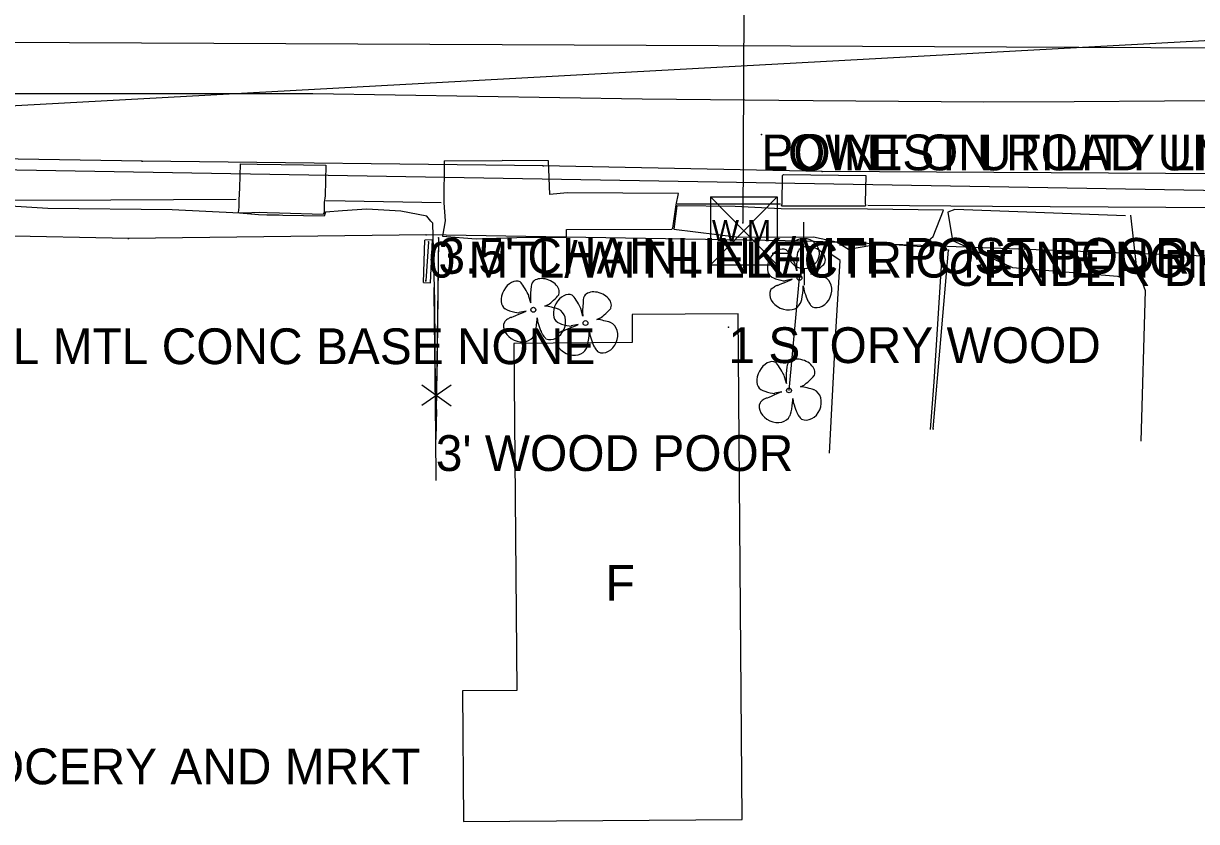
# Model space of a CAD drawing. Extents: x 1304270 to 1306561, y 1876019 to 1876752.
# Drawn here: x 1305136 to 1305299.9, y 1876306.3 to 1876417.9 of the extents above; entities that cross this region are included whole.
import ezdxf

# ---------------------------------------------------------------- set-up
doc = ezdxf.new("R2010")
doc.units = 0
for name, color, linetype in [('Default', 7, 'Continuous'), ('S_BUILDING', 7, 'Continuous'), ('S_BUILDING_ANNOT', 7, 'Continuous'), ('S_DRIVEWAY', 7, 'Continuous'), ('S_EDGE_CONCRETE', 7, 'Continuous'), ('S_EDGE_PAVEMENT', 7, 'Continuous'), ('S_ELECTRIC_UTILITIES_ANNOT', 7, 'Continuous'), ('S_FENCE', 7, 'Continuous'), ('S_FENCE_ANNOT', 7, 'Continuous'), ('S_FIBER_OPTIC_CABLE', 7, 'Continuous'), ('S_GAS_UTILITIES', 7, 'Continuous'), ('S_MISC_STRUCTURES', 7, 'Continuous'), ('S_MISC_STRUCTURES_ANNOT', 7, 'Continuous'), ('S_MSC_PT_SYM', 7, 'Continuous'), ('S_PAVEMENT_CROWN', 7, 'Continuous'), ('S_SANITARY_SEWER', 7, 'Continuous'), ('S_SHOULDER', 7, 'Continuous'), ('S_SIGN', 7, 'Continuous'), ('S_SIGN_ANNOT', 7, 'Continuous'), ('S_STR_PT_SYM', 7, 'Continuous'), ('S_SURVEY_TEXT_ANNOT', 7, 'Continuous'), ('S_TREE', 7, 'Continuous'), ('S_UTILITY_POLE', 7, 'Continuous'), ('S_UTL_PT_SYM', 7, 'Continuous'), ('S_WATER_UTILITIES', 7, 'Continuous')]:
    doc.layers.add(name, color=color, linetype=linetype)

msp = doc.modelspace()

# ---------------------------------------------------------------- linework, layer by layer
at = {"layer": 'Default'}
msp.add_line((1304873.94, 1876392.06), (1305473.53, 1876424.94), dxfattribs=at)
at = {"layer": 'S_BUILDING'}
msp.add_lwpolyline([(1305236.42, 1876306.65), (1305235.86, 1876377.3), (1305221.06, 1876377.18), (1305221.09, 1876373.28), (1305204.56, 1876373.15), (1305204.95, 1876324.66), (1305197.36, 1876324.6), (1305197.5, 1876306.34)], close=True, dxfattribs=at)
at = {"layer": 'S_DRIVEWAY'}
for points in [[(1305290.67, 1876391.05), (1305291.49, 1876384.02), (1305292.72, 1876380.55), (1305292.14, 1876359.47)], [(1305248.63, 1876357.79), (1305249.51, 1876374.72), (1305250.14, 1876384.75), (1305248.83, 1876385.6)], [(1305264.44, 1876386.92), (1305263.21, 1876367.8), (1305262.7, 1876361.12)]]:
    msp.add_lwpolyline(points, dxfattribs=at)
at = {"layer": 'S_EDGE_CONCRETE'}
for points in [[(1305194.83, 1876398.65), (1305194.76, 1876392.78), (1305194.93, 1876390.27), (1305194.57, 1876388.15), (1305199.27, 1876387.78), (1305206.42, 1876388.01), (1305211.9, 1876387.93), (1305211.92, 1876389.06), (1305226.59, 1876389.12), (1305226.74, 1876389.23), (1305227.2, 1876392.52), (1305227.53, 1876394.09), (1305212.01, 1876394.2), (1305209.58, 1876393.96), (1305209.39, 1876398.66), (1305202.9, 1876398.72)], [(1305194.83, 1876398.65), (1305202.9, 1876398.72)], [(1305166.1, 1876391.45), (1305166.16, 1876392.2), (1305166.18, 1876392.58), (1305166.2, 1876393.14), (1305166.25, 1876394.88), (1305166.36, 1876398.22), (1305168.68, 1876398.19), (1305172.03, 1876398.16), (1305178.27, 1876398.07), (1305178.18, 1876393.78), (1305178.07, 1876392.83), (1305178.07, 1876392.17), (1305178.07, 1876391.48), (1305177.9, 1876391.15), (1305171.83, 1876391.36), (1305170.07, 1876391.4), (1305169.01, 1876391.44), (1305167.97, 1876391.41)], [(1305241.95, 1876392.35), (1305242.01, 1876392.65), (1305242.07, 1876396.61), (1305242.2, 1876396.73), (1305253.69, 1876396.59), (1305253.63, 1876392.8), (1305253.64, 1876392.39)], [(1305241.95, 1876392.35), (1305253.64, 1876392.39)], [(1305166.1, 1876391.45), (1305167.97, 1876391.41)], [(1305191.92, 1876381.68), (1305192.91, 1876381.59), (1305193.18, 1876387.64), (1305192.11, 1876387.59)], [(1305191.92, 1876381.68), (1305192.11, 1876387.59)]]:
    msp.add_lwpolyline(points, dxfattribs=at)
at = {"layer": 'S_EDGE_PAVEMENT'}
for points in [[(1305083.08, 1876393.71), (1305104.14, 1876393.18), (1305117.43, 1876393.17), (1305130.73, 1876393.16), (1305148.24, 1876393.22), (1305165.75, 1876393.28)], [(1305193.68, 1876353.97), (1305193.6, 1876366.51), (1305193.52, 1876379.04), (1305193.25, 1876389.96), (1305192.97, 1876390.22), (1305192.38, 1876390.91), (1305188.76, 1876391.64), (1305184.02, 1876391.89), (1305180.63, 1876391.66), (1305178.22, 1876391.48), (1305178.06, 1876390.92), (1305172.3, 1876391.03), (1305171.77, 1876391.06), (1305170.06, 1876391.08), (1305168.86, 1876391.09), (1305166.22, 1876391.34), (1305156.83, 1876391.81), (1305139.46, 1876391.99), (1305129.66, 1876392.59), (1305110.42, 1876393.02), (1305088.15, 1876393.37), (1305086.11, 1876393.25), (1305084.26, 1876393.15)], [(1305178.28, 1876393.1), (1305194.37, 1876392.85)], [(1305241.8, 1876392.59), (1305227.36, 1876392.62)], [(1305254, 1876392.45), (1305271.4, 1876392.34), (1305295.59, 1876392.2), (1305319.77, 1876392.05), (1305338.06, 1876392.13)]]:
    msp.add_lwpolyline(points, dxfattribs=at)
at = {"layer": 'S_FENCE'}
for p, q in [((1305194.01, 1876387.88), (1305193.67, 1876359.83)), ((1305193.64, 1876360.32), (1305193.41, 1876380.91)), ((1305191.71, 1876367.36), (1305195.77, 1876364.44)), ((1305191.71, 1876367.36), (1305195.77, 1876364.44)), ((1305195.81, 1876367.31), (1305191.68, 1876364.49)), ((1305195.81, 1876367.31), (1305191.68, 1876364.49))]:
    msp.add_line(p, q, dxfattribs=at)
for points in [[(1305194.01, 1876387.88), (1305193.77, 1876367.9)], [(1305194.01, 1876387.88), (1305193.77, 1876367.9)], [(1305193.64, 1876360.32), (1305193.41, 1876380.31)], [(1305193.64, 1876360.32), (1305193.41, 1876380.31)], [(1305193.72, 1876363.9), (1305193.67, 1876359.83)], [(1305193.72, 1876363.9), (1305193.67, 1876359.83)]]:
    msp.add_lwpolyline(points, dxfattribs=at)
at = {"layer": 'S_FIBER_OPTIC_CABLE'}
for p, q in [((1305152.63, 1876398.59), (1305060.48, 1876400.23)), ((1305352.56, 1876393.61), (1305019.82, 1876399.32)), ((1305208.66, 1876397.95), (1305152.63, 1876398.59)), ((1305247.6, 1876397.15), (1305208.66, 1876397.95)), ((1305352.1, 1876396.58), (1305247.6, 1876397.15))]:
    msp.add_line(p, q, dxfattribs=at)
at = {"layer": 'S_GAS_UTILITIES'}
for p, q in [((1305150.7, 1876387.79), (1305125.76, 1876388.29)), ((1305192.3, 1876388.32), (1305150.7, 1876387.79)), ((1305245.22, 1876387.43), (1305192.3, 1876388.32)), ((1305315.46, 1876384.79), (1305245.22, 1876387.43))]:
    msp.add_line(p, q, dxfattribs=at)
at = {"layer": 'S_MISC_STRUCTURES'}
msp.add_line((1305263.11, 1876361.19), (1305265.25, 1876386.18), dxfattribs=at)
at = {"layer": 'S_MSC_PT_SYM'}
for points in [[(1305239.12, 1876402.33), (1305239.12, 1876402.38), (1305239.12, 1876402.33), (1305239.07, 1876402.33), (1305239.12, 1876402.33), (1305239.12, 1876402.28), (1305239.12, 1876402.33), (1305239.17, 1876402.33)], [(1305192.64, 1876387.34), (1305192.64, 1876387.39), (1305192.64, 1876387.34), (1305192.59, 1876387.34), (1305192.64, 1876387.34), (1305192.64, 1876387.29), (1305192.64, 1876387.34), (1305192.69, 1876387.34)], [(1305194.01, 1876387.88), (1305194.01, 1876387.93), (1305194.01, 1876387.88), (1305193.96, 1876387.88), (1305194.01, 1876387.88), (1305194.01, 1876387.83), (1305194.01, 1876387.88), (1305194.06, 1876387.88)], [(1305265.25, 1876386.18), (1305265.25, 1876386.23), (1305265.25, 1876386.18), (1305265.2, 1876386.18), (1305265.25, 1876386.18), (1305265.25, 1876386.13), (1305265.25, 1876386.18), (1305265.3, 1876386.18)], [(1305192.23, 1876381.88), (1305192.23, 1876381.93), (1305192.23, 1876381.88), (1305192.18, 1876381.88), (1305192.23, 1876381.88), (1305192.23, 1876381.83), (1305192.23, 1876381.88), (1305192.28, 1876381.88)], [(1305193.41, 1876380.91), (1305193.41, 1876380.96), (1305193.41, 1876380.91), (1305193.36, 1876380.91), (1305193.41, 1876380.91), (1305193.41, 1876380.86), (1305193.41, 1876380.91), (1305193.46, 1876380.91)], [(1305263.11, 1876361.19), (1305263.11, 1876361.24), (1305263.11, 1876361.19), (1305263.06, 1876361.19), (1305263.11, 1876361.19), (1305263.11, 1876361.14), (1305263.11, 1876361.19), (1305263.16, 1876361.19)], [(1305193.64, 1876360.32), (1305193.64, 1876360.37), (1305193.64, 1876360.32), (1305193.59, 1876360.32), (1305193.64, 1876360.32), (1305193.64, 1876360.27), (1305193.64, 1876360.32), (1305193.69, 1876360.32)], [(1305193.67, 1876359.83), (1305193.67, 1876359.88), (1305193.67, 1876359.83), (1305193.62, 1876359.83), (1305193.67, 1876359.83), (1305193.67, 1876359.78), (1305193.67, 1876359.83), (1305193.72, 1876359.83)]]:
    msp.add_lwpolyline(points, dxfattribs=at)
at = {"layer": 'S_PAVEMENT_CROWN'}
msp.add_lwpolyline([(1305132.34, 1876408.05), (1305154.42, 1876408.07), (1305176.49, 1876408.08), (1305199.49, 1876407.69), (1305222.49, 1876407.31), (1305246.33, 1876407.09), (1305270.17, 1876406.88), (1305282.8, 1876406.96), (1305295.42, 1876407.05), (1305308.05, 1876407.14), (1305320.68, 1876407.22), (1305336.61, 1876406.9), (1305349.96, 1876406.83), (1305363.32, 1876406.76), (1305376.67, 1876406.68), (1305390.03, 1876406.61), (1305413.65, 1876406.71), (1305437.28, 1876406.8)], dxfattribs=at)
at = {"layer": 'S_SANITARY_SEWER'}
msp.add_line((1304983.66, 1876415.96), (1305346.23, 1876414.24), dxfattribs=at)
at = {"layer": 'S_SHOULDER'}
msp.add_lwpolyline([(1305227.33, 1876392.38), (1305226.88, 1876389.11), (1305235.99, 1876387.98), (1305246.39, 1876388.03), (1305249.61, 1876387.34), (1305251.28, 1876386.31), (1305255.9, 1876387.13), (1305261.47, 1876386.7), (1305263.12, 1876388.09), (1305264.56, 1876391.75), (1305253.94, 1876391.9), (1305241.88, 1876391.94), (1305235.45, 1876392.26)], close=True, dxfattribs=at)
for points in [[(1305289.96, 1876390.98), (1305266.16, 1876391.85), (1305265.14, 1876391.5)], [(1305265.14, 1876391.5), (1305265.81, 1876387.53), (1305274.18, 1876383.76), (1305289.4, 1876382.49)]]:
    msp.add_lwpolyline(points, dxfattribs=at)
at = {"layer": 'S_SIGN'}
msp.add_line((1305192.64, 1876387.34), (1305192.23, 1876381.88), dxfattribs=at)
at = {"layer": 'S_STR_PT_SYM'}
msp.add_lwpolyline([(1305234.52, 1876375.4), (1305234.52, 1876375.45), (1305234.52, 1876375.4), (1305234.47, 1876375.4), (1305234.52, 1876375.4), (1305234.52, 1876375.35), (1305234.52, 1876375.4), (1305234.57, 1876375.4)], dxfattribs=at)
at = {"layer": 'S_TREE'}
for p, q in [((1305244.08, 1876383.29), (1305243.84, 1876384.18)), ((1305243.43, 1876382.13), (1305242.46, 1876381.91)), ((1305242.98, 1876366.58), (1305244.45, 1876382.31)), ((1305246.03, 1876382.83), (1305246.41, 1876382.99)), ((1305244.97, 1876381.2), (1305245.05, 1876380.76)), ((1305206.9, 1876378.83), (1305206.66, 1876379.72)), ((1305206.25, 1876377.66), (1305205.28, 1876377.45)), ((1305208.85, 1876378.37), (1305209.23, 1876378.53)), ((1305214.19, 1876376.96), (1305213.95, 1876377.86)), ((1305207.79, 1876376.73), (1305207.87, 1876376.29)), ((1305213.54, 1876375.8), (1305212.57, 1876375.58)), ((1305216.14, 1876376.5), (1305216.52, 1876376.67)), ((1305215.08, 1876374.87), (1305215.16, 1876374.43)), ((1305242.61, 1876367.56), (1305242.37, 1876368.46)), ((1305241.96, 1876366.4), (1305240.99, 1876366.18)), ((1305244.56, 1876367.1), (1305244.94, 1876367.27)), ((1305243.5, 1876365.47), (1305243.57, 1876365.03))]:
    msp.add_line(p, q, dxfattribs=at)
for centre in [(1305244.45, 1876382.31), (1305207.27, 1876377.85), (1305214.56, 1876375.99), (1305242.98, 1876366.58)]:
    msp.add_circle(centre, 0.341, dxfattribs=at)
for centre, major_axis, ratio, start_param, end_param in [((1305241.56, 1876384.33), (-1.03, -1.88), 0.662338, 3.141593, 6.283185), ((1305243.22, 1876385.2), (0.62, -1.01), 0.083512, 0, 3.141593), ((1305244.15, 1876384.62), (-0.07, -1.33), 0.068203, 3.141593, 6.283185), ((1305246.11, 1876385.2), (1.89, -0.74), 0.673998, 0, 3.141593), ((1305247.21, 1876383.72), (-0.798, -0.73), 0.092159, 0, 3.141593), ((1305204.38, 1876379.86), (-1.03, -1.88), 0.662338, 3.141593, 6.283185), ((1305208.93, 1876380.73), (1.89, -0.74), 0.673998, 0, 3.141593), ((1305241.5, 1876382.18), (0.964, -0.267), 0.113563, 3.141593, 6.283185), ((1305242.4, 1876381.68), (1.04, 0.44), 0.002756, 3.141593, 6.283185), ((1305246.99, 1876382.6), (0.96, -0.23), 0.056001, 0, 3.141593), ((1305247.07, 1876380.33), (0.88, 2.05), 0.81717, 3.141593, 6.283185), ((1305206.04, 1876380.73), (0.62, -1.01), 0.083512, 0, 3.141593), ((1305206.97, 1876380.15), (-0.07, -1.33), 0.068203, 3.141593, 6.283185), ((1305216.22, 1876378.87), (1.89, -0.74), 0.673998, 0, 3.141593), ((1305242.47, 1876379.65), (2.07, -0.93), 0.760068, 3.141593, 6.283185), ((1305240.88, 1876380.91), (0.477, 0.328), 0.136309, 0, 3.141593), ((1305244.73, 1876380.03), (0.19, 1.31), 0.114148, 3.141593, 5.822668), ((1305245.3, 1876379.99), (0.254, -0.771), 0.051603, 3.141593, 6.283185), ((1305210.03, 1876379.26), (-0.798, -0.73), 0.092159, 0, 3.141593), ((1305211.67, 1876378), (-1.03, -1.88), 0.662338, 3.141593, 6.283185), ((1305213.33, 1876378.87), (0.62, -1.01), 0.083512, 0, 3.141593), ((1305214.26, 1876378.29), (-0.07, -1.33), 0.068203, 3.141593, 6.283185), ((1305245.88, 1876378.75), (-0.321, 0.467), 0.094289, 0, 3.141593), ((1305204.32, 1876377.71), (0.964, -0.267), 0.113563, 3.141593, 6.283185), ((1305205.22, 1876377.22), (1.04, 0.44), 0.002756, 3.141593, 6.283185), ((1305209.81, 1876378.14), (0.96, -0.23), 0.056001, 0, 3.141593), ((1305209.89, 1876375.86), (0.88, 2.05), 0.81717, 3.141593, 6.283185), ((1305217.32, 1876377.4), (-0.798, -0.73), 0.092159, 0, 3.141593), ((1305205.29, 1876375.19), (2.07, -0.93), 0.760068, 3.141593, 6.283185), ((1305203.7, 1876376.45), (0.477, 0.328), 0.136309, 0, 3.141593), ((1305207.55, 1876375.57), (0.19, 1.31), 0.114148, 3.141593, 5.822668), ((1305208.12, 1876375.52), (0.254, -0.771), 0.051603, 3.141593, 6.283185), ((1305211.61, 1876375.85), (0.964, -0.267), 0.113563, 3.141593, 6.283185), ((1305212.51, 1876375.36), (1.04, 0.44), 0.002756, 3.141593, 6.283185), ((1305217.1, 1876376.27), (0.96, -0.23), 0.056001, 0, 3.141593), ((1305217.18, 1876374), (0.88, 2.05), 0.81717, 3.141593, 6.283185), ((1305208.7, 1876374.28), (-0.321, 0.467), 0.094289, 0, 3.141593), ((1305212.58, 1876373.33), (2.07, -0.93), 0.760068, 3.141593, 6.283185), ((1305210.99, 1876374.59), (0.477, 0.328), 0.136309, 0, 3.141593), ((1305214.84, 1876373.7), (0.19, 1.31), 0.114148, 3.141593, 5.822668), ((1305215.41, 1876373.66), (0.254, -0.771), 0.051603, 3.141593, 6.283185), ((1305215.99, 1876372.42), (-0.321, 0.467), 0.094289, 0, 3.141593), ((1305240.09, 1876368.6), (-1.03, -1.88), 0.662338, 3.141593, 6.283185), ((1305244.64, 1876369.47), (1.89, -0.74), 0.673998, 0, 3.141593), ((1305241.74, 1876369.47), (0.62, -1.01), 0.083512, 0, 3.141593), ((1305242.68, 1876368.89), (-0.07, -1.33), 0.068203, 3.141593, 6.283185), ((1305245.73, 1876368), (-0.798, -0.73), 0.092159, 0, 3.141593), ((1305240.02, 1876366.45), (0.964, -0.267), 0.113563, 3.141593, 6.283185), ((1305240.92, 1876365.96), (1.04, 0.44), 0.002756, 3.141593, 6.283185), ((1305245.52, 1876366.87), (0.96, -0.23), 0.056001, 0, 3.141593), ((1305245.6, 1876364.6), (0.88, 2.05), 0.81717, 3.141593, 6.283185), ((1305241, 1876363.92), (2.07, -0.93), 0.760068, 3.141593, 6.283185), ((1305239.41, 1876365.19), (0.477, 0.328), 0.136309, 0, 3.141593), ((1305243.26, 1876364.3), (0.19, 1.31), 0.114148, 3.141593, 5.822668), ((1305243.83, 1876364.26), (0.254, -0.771), 0.051603, 3.141593, 6.283185), ((1305244.4, 1876363.02), (-0.321, 0.467), 0.094289, 0, 3.141593)]:
    msp.add_ellipse(centre, major_axis=major_axis, ratio=ratio, start_param=start_param, end_param=end_param, dxfattribs=at)
at = {"layer": 'S_UTILITY_POLE'}
for p, q in [((1305245.05, 1876387.82), (1305245.05, 1876390.07)), ((1305242.96, 1876385.69), (1305240.63, 1876385.69)), ((1305245.13, 1876381.28), (1305245.13, 1876383.6))]:
    msp.add_line(p, q, dxfattribs=at)
msp.add_circle((1305245.05, 1876385.71), 2.13, dxfattribs=at)
at = {"layer": 'S_UTL_PT_SYM'}
for points in [[(1305239.12, 1876402.33), (1305239.12, 1876402.38), (1305239.12, 1876402.33), (1305239.07, 1876402.33), (1305239.12, 1876402.33), (1305239.12, 1876402.28), (1305239.12, 1876402.33), (1305239.17, 1876402.33)], [(1305152.63, 1876398.59), (1305152.63, 1876398.64), (1305152.63, 1876398.59), (1305152.58, 1876398.59), (1305152.63, 1876398.59), (1305152.63, 1876398.54), (1305152.63, 1876398.59), (1305152.68, 1876398.59)], [(1305208.66, 1876397.95), (1305208.66, 1876398), (1305208.66, 1876397.95), (1305208.61, 1876397.95), (1305208.66, 1876397.95), (1305208.66, 1876397.9), (1305208.66, 1876397.95), (1305208.71, 1876397.95)], [(1305247.6, 1876397.15), (1305247.6, 1876397.2), (1305247.6, 1876397.15), (1305247.55, 1876397.15), (1305247.6, 1876397.15), (1305247.6, 1876397.1), (1305247.6, 1876397.15), (1305247.65, 1876397.15)], [(1305236.52, 1876389.99), (1305236.52, 1876390.04), (1305236.52, 1876389.99), (1305236.47, 1876389.99), (1305236.52, 1876389.99), (1305236.52, 1876389.94), (1305236.52, 1876389.99), (1305236.57, 1876389.99)], [(1305150.7, 1876387.79), (1305150.7, 1876387.84), (1305150.7, 1876387.79), (1305150.65, 1876387.79), (1305150.7, 1876387.79), (1305150.7, 1876387.74), (1305150.7, 1876387.79), (1305150.75, 1876387.79)], [(1305192.3, 1876388.32), (1305192.3, 1876388.37), (1305192.3, 1876388.32), (1305192.25, 1876388.32), (1305192.3, 1876388.32), (1305192.3, 1876388.27), (1305192.3, 1876388.32), (1305192.35, 1876388.32)], [(1305245.22, 1876387.43), (1305245.22, 1876387.48), (1305245.22, 1876387.43), (1305245.17, 1876387.43), (1305245.22, 1876387.43), (1305245.22, 1876387.38), (1305245.22, 1876387.43), (1305245.27, 1876387.43)]]:
    msp.add_lwpolyline(points, dxfattribs=at)
at = {"layer": 'S_WATER_UTILITIES'}
for p, q in [((1305236.69, 1876420.13), (1305236.52, 1876389.99)), ((1305232.01, 1876393.64), (1305241.34, 1876393.64)), ((1305232.01, 1876393.64), (1305232.01, 1876384.14)), ((1305232.01, 1876393.64), (1305241.34, 1876384.14)), ((1305241.34, 1876393.64), (1305232.01, 1876384.14)), ((1305241.34, 1876393.64), (1305241.34, 1876384.14)), ((1305232.01, 1876384.14), (1305241.34, 1876384.14))]:
    msp.add_line(p, q, dxfattribs=at)

# ---------------------------------------------------------------- texts
at = {"layer": 'S_BUILDING_ANNOT'}
for s, p in [('1 STORY WOOD', (1305234.52, 1876370.4)), ('F', (1305217.35, 1876337.19)), ('BRICK AND MTL CORNER CROCERY AND MRKT', (1305036.95, 1876311.54))]:
    msp.add_text(s, height=5, dxfattribs=at).set_placement(p)
at = {"layer": 'S_ELECTRIC_UTILITIES_ANNOT'}
msp.add_text('POINT ON ROAD UNDER LOWES', height=5, dxfattribs=at).set_placement((1305239.12, 1876397.33))
at = {"layer": 'S_FENCE_ANNOT'}
for s, p in [("3.5' CHAINLINK/MTL POST POOR", (1305194.01, 1876382.88)), ("3' WOOD POOR", (1305193.64, 1876355.32))]:
    msp.add_text(s, height=5, dxfattribs=at).set_placement(p)
at = {"layer": 'S_MISC_STRUCTURES_ANNOT'}
msp.add_text('CENDER BLOCK WR', height=5, dxfattribs=at).set_placement((1305265.25, 1876381.18))
at = {"layer": 'S_SIGN_ANNOT'}
for s, p in [('0 MTL/WITH ELECTRIC NONE NONE', (1305192.64, 1876382.34)), ('0 MTL MTL CONC BASE NONE', (1305119.32, 1876370.25))]:
    msp.add_text(s, height=5, dxfattribs=at).set_placement(p)
at = {"layer": 'S_SURVEY_TEXT_ANNOT'}
msp.add_text('LOWEST UTILITY LINE', height=5, dxfattribs=at).set_placement((1305239.12, 1876397.33))
at = {"layer": 'S_WATER_UTILITIES'}
msp.add_text('W M', height=3, rotation=360, dxfattribs=at).set_placement((1305232.21, 1876387.4))

doc.saveas('drawing.dxf')
